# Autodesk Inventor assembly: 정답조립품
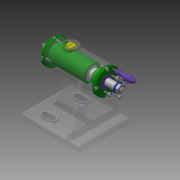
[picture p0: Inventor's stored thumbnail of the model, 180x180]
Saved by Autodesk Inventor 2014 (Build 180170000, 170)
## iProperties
Created: 2019-10
Part Number: 정답조립품
Document SubType Name: Assembly
Designer: kh
Author: kh
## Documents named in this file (18)
- C:\Users\kh\Desktop\491004V1027\정답조립품.iam
- C:\Users\kh\Desktop\491004V1027\본체.ipt
- C:\Users\kh\Desktop\491004V1027\나사.ipt
- C:\Users\kh\Desktop\491004V1027\나사축.ipt
- C:\Users\kh\Desktop\491004V1027\너트 M8.ipt
- C:\Users\kh\Desktop\491004V1027\돌림판.ipt
- C:\Users\kh\Desktop\491004V1027\멈춤나사 M3.ipt
- C:\Users\kh\Desktop\491004V1027\볼트 M3.ipt
- C:\Users\kh\Desktop\491004V1027\부시.ipt
- C:\Users\kh\Desktop\491004V1027\센터.ipt
- C:\Users\kh\Desktop\491004V1027\센터홀더.ipt
- C:\Users\kh\Desktop\491004V1027\슬리브.ipt
- C:\Users\kh\Desktop\491004V1027\와셔.ipt
- C:\Users\kh\Desktop\491004V1027\중공축.ipt
- C:\Users\kh\Desktop\491004V1027\커버.ipt
- C:\Users\kh\Desktop\491004V1027\키 4 x 4 x 10.ipt
- C:\Users\kh\Desktop\491004V1027\플랜지.ipt
- C:\Users\kh\Desktop\491004V1027\핸들.ipt
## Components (2 placed, 2 different names)
1. 플랜지:1 — Insert:2, Insert:8, Insert:11, Insert:17, Mate:7
2. 핸들:1 — Insert:12
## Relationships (6: Insert 5, Mate 1)
- Insert:2: 플랜지:1
- Insert:8: 플랜지:1
- Insert:11: 플랜지:1
- Insert:12: 핸들:1
- Insert:17: 플랜지:1
- Mate:7: 플랜지:1
